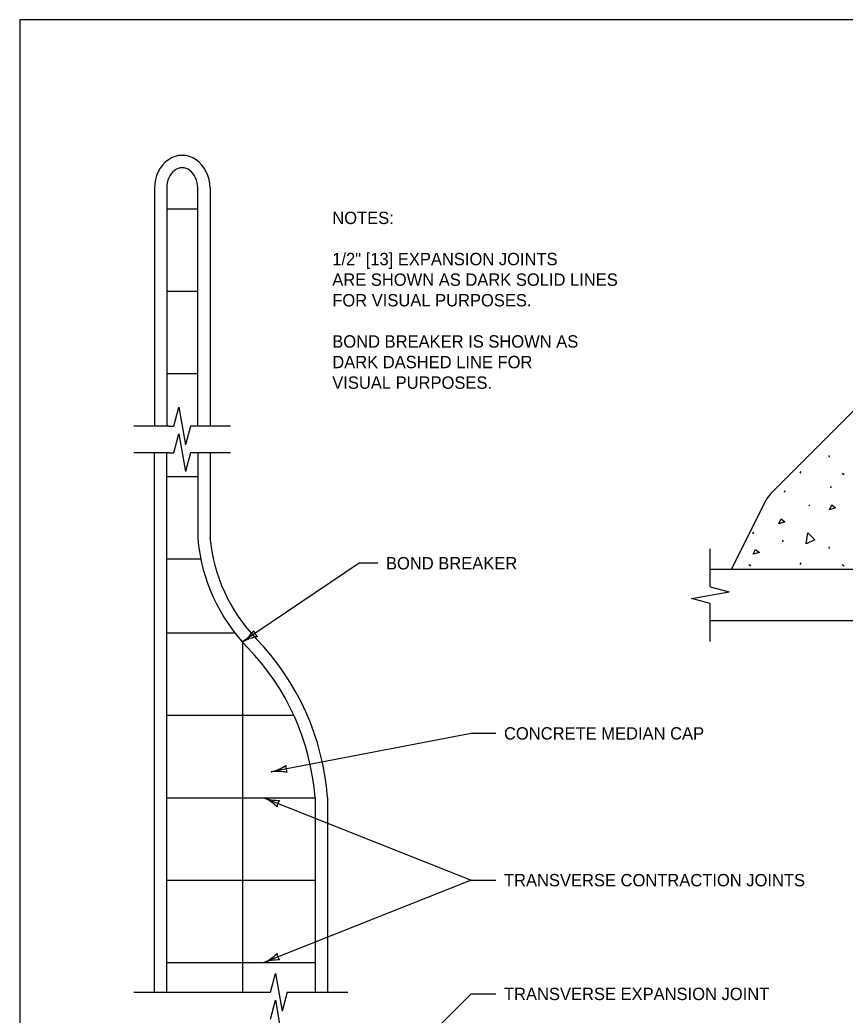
# Model space of a CAD drawing. Extents: x 49991.4 to 50021, y 49987.6 to 50011.4.
# Drawn here: x 50000.336 to 50004.343, y 50006.431 to 50011.263 of the extents above; entities that cross this region are included whole.
import ezdxf

# ---------------------------------------------------------------- set-up
doc = ezdxf.new("R2010")
doc.units = 0
for name, color, linetype in [('Level 1', 7, 'Continuous'), ('Level 2', 7, 'Continuous'), ('Level 3', 7, 'Continuous'), ('Level 6', 7, 'Continuous')]:
    doc.layers.add(name, color=color, linetype=linetype)

msp = doc.modelspace()

# ---------------------------------------------------------------- linework, layer by layer
at = {"layer": 'Level 1'}
for p, q in [((50000.989, 50010.4457), (50000.989, 50009.2907)), ((50001.049, 50010.4457), (50001.049, 50009.2907)), ((50001.199, 50009.2907), (50001.199, 50010.4457)), ((50001.259, 50010.4457), (50001.259, 50009.2907)), ((50001.049, 50010.3457), (50001.199, 50010.3457)), ((50001.049, 50009.9457), (50001.199, 50009.9457)), ((50004.637, 50009.6178), (50003.9828, 50008.9636)), ((50001.049, 50009.5457), (50001.199, 50009.5457)), ((50000.989, 50006.5411), (50000.989, 50009.1609)), ((50001.049, 50006.5411), (50001.049, 50009.1609)), ((50001.199, 50009.1609), (50001.199, 50008.7457)), ((50001.259, 50009.1609), (50001.259, 50008.7457)), ((50004.2649, 50009.1474), (50004.2658, 50009.1389)), ((50001.049, 50009.0462), (50001.199, 50009.0462)), ((50004.1258, 50009.0613), (50004.1296, 50009.0698)), ((50004.3295, 50009.0613), (50004.3333, 50009.0556)), ((50004.3333, 50009.0592), (50004.3371, 50009.0535)), ((50004.2736, 50008.9911), (50004.2774, 50008.9996)), ((50004.0491, 50008.9693), (50004.0529, 50008.9778)), ((50003.958, 50008.9292), (50003.7905, 50008.5943)), ((50004.1675, 50008.9087), (50004.1713, 50008.903)), ((50003.8956, 50008.7675), (50003.8994, 50008.776)), ((50004.0396, 50008.7287), (50004.0434, 50008.7372)), ((50004.2649, 50008.7049), (50004.2658, 50008.6964)), ((50001.049, 50008.6462), (50001.2137, 50008.6462)), ((50003.8757, 50008.6188), (50003.8795, 50008.6131)), ((50003.8795, 50008.6166), (50003.8833, 50008.6109)), ((50004.1258, 50008.6188), (50004.1296, 50008.6273)), ((50004.3295, 50008.6188), (50004.3333, 50008.6131)), ((50004.3333, 50008.6166), (50004.3371, 50008.6109)), ((50003.7906, 50008.5944), (50003.6881, 50008.5944)), ((50005.9155, 50008.5943), (50003.7905, 50008.5943)), ((50006.8155, 50008.3444), (50003.6881, 50008.3444)), ((50001.3799, 50008.2857), (50001.049, 50008.2857)), ((50001.4159, 50008.2423), (50001.4159, 50006.5411)), ((50001.6663, 50007.8857), (50001.049, 50007.8857)), ((50001.049, 50007.4857), (50001.769, 50007.4857)), ((50001.769, 50007.4857), (50001.769, 50006.5411)), ((50001.829, 50007.4878), (50001.829, 50006.5411)), ((50001.049, 50007.0857), (50001.769, 50007.0857)), ((50001.049, 50006.6857), (50001.769, 50006.6857))]:
    msp.add_line(p, q, dxfattribs=at)
msp.add_lwpolyline([(50008.6146, 50011.2628), (50000.3356, 50011.2628), (50000.3356, 50000.0624), (50008.6146, 50000.0624)], close=True, dxfattribs=at)
for points in [[(50004.267, 50008.884), (50004.2784, 50008.9077), (50004.2973, 50008.8935), (50004.267, 50008.884)], [(50004.0209, 50008.8163), (50004.0322, 50008.84), (50004.0512, 50008.8258), (50004.0209, 50008.8163)], [(50004.1549, 50008.7189), (50004.1624, 50008.773), (50004.1963, 50008.738), (50004.1558, 50008.7192)], [(50003.8975, 50008.668), (50003.9089, 50008.6917), (50003.9278, 50008.6775), (50003.8975, 50008.668)]]:
    msp.add_lwpolyline(points, dxfattribs=at)
for centre, radius, start, end in [((50004.0768, 50008.8698), 0.1328, 135, 153.4329), ((50002.0724, 50008.8235), 0.8168, 185.0967, 223.8607), ((50002.0724, 50008.8235), 0.8768, 185.0967, 223.8607), ((50000.6011, 50007.3989), 1.2312, 4.141, 44.2364), ((50000.6011, 50007.3989), 1.1712, 4.2458, 44.2364)]:
    msp.add_arc(centre, radius, start, end, dxfattribs=at)
for major_axis, ratio in [((0, 0.1595), 0.846422), ((0, 0.0995), 0.753807)]:
    msp.add_ellipse((50001.124, 50010.4457), major_axis=major_axis, ratio=ratio, start_param=4.712389, end_param=7.853982, dxfattribs=at)
at = {"layer": 'Level 3'}
for p, q in [((50001.9833, 50008.6255), (50001.4159, 50008.2423)), ((50002.0735, 50008.6255), (50001.9833, 50008.6255)), ((50002.5266, 50007.7984), (50001.556, 50007.6117)), ((50002.6466, 50007.7984), (50002.5266, 50007.7984)), ((50001.52, 50007.4857), (50002.5266, 50007.0857)), ((50002.5266, 50007.0857), (50001.52, 50006.6857)), ((50002.5266, 50007.0857), (50002.6466, 50007.0857)), ((50001.4789, 50005.4857), (50002.5266, 50006.5333)), ((50002.5266, 50006.5333), (50002.6466, 50006.5333))]:
    msp.add_line(p, q, dxfattribs=at)
for centre, radius, start, end in [((50001.2837, 50008.4342), 0.233, 304.565, 323.8148), ((50001.5249, 50008.0486), 0.2223, 99.1937, 119.3772), ((50001.5249, 50008.3098), 0.0548, 193.8765, 229.5988), ((50001.5015, 50007.8382), 0.233, 283.5278, 302.7777), ((50001.682, 50007.6355), 0.0548, 172.8394, 208.5617), ((50001.5882, 50007.3917), 0.2223, 78.1565, 98.3401), ((50001.4294, 50007.2826), 0.2223, 45.756, 65.9395), ((50001.5954, 50007.7061), 0.233, 251.1273, 270.3772), ((50001.6392, 50007.4382), 0.0548, 140.4388, 176.1612), ((50001.4233, 50006.8976), 0.233, 294.5273, 313.7772), ((50001.6392, 50006.7331), 0.0548, 183.8388, 219.5612), ((50001.5937, 50006.4759), 0.2223, 89.156, 109.3395)]:
    msp.add_arc(centre, radius, start, end, dxfattribs=at)
at = {"layer": 'Level 6'}
for p, q in [((50001.0836, 50009.2907), (50001.1078, 50009.3821)), ((50001.1078, 50009.3821), (50001.1402, 50009.1993)), ((50001.0593, 50009.2907), (50000.889, 50009.2907)), ((50001.0593, 50009.2907), (50001.0755, 50009.2907)), ((50001.0755, 50009.2907), (50001.0836, 50009.2907)), ((50001.1646, 50009.2907), (50001.1402, 50009.1993)), ((50001.1727, 50009.2907), (50001.1646, 50009.2907)), ((50001.1889, 50009.2907), (50001.1727, 50009.2907)), ((50001.359, 50009.2907), (50001.1889, 50009.2907)), ((50001.0836, 50009.1609), (50001.1078, 50009.2523)), ((50001.1078, 50009.2523), (50001.1402, 50009.0695)), ((50001.0593, 50009.1609), (50000.889, 50009.1609)), ((50001.0593, 50009.1609), (50001.0755, 50009.1609)), ((50001.0755, 50009.1609), (50001.0836, 50009.1609)), ((50001.1646, 50009.1609), (50001.1402, 50009.0695)), ((50001.1727, 50009.1609), (50001.1646, 50009.1609)), ((50001.1889, 50009.1609), (50001.1727, 50009.1609)), ((50001.359, 50009.1609), (50001.1889, 50009.1609)), ((50003.6881, 50008.5097), (50003.6881, 50008.6944)), ((50003.6881, 50008.5097), (50003.7795, 50008.4853)), ((50003.5967, 50008.4529), (50003.7795, 50008.4853)), ((50003.6881, 50008.4287), (50003.5967, 50008.4529)), ((50003.6881, 50008.2444), (50003.6881, 50008.4287)), ((50001.552, 50006.5411), (50001.5762, 50006.6325)), ((50001.5762, 50006.6325), (50001.6086, 50006.4497)), ((50000.889, 50006.5411), (50001.552, 50006.5411)), ((50001.633, 50006.5411), (50001.6086, 50006.4497)), ((50001.633, 50006.5411), (50001.929, 50006.5411)), ((50001.552, 50006.4113), (50001.5762, 50006.5027)), ((50001.5762, 50006.5027), (50001.6086, 50006.3199))]:
    msp.add_line(p, q, dxfattribs=at)

# ---------------------------------------------------------------- texts
at = {"layer": 'Level 2'}
for s, p in [('NOTES:', (50001.8527, 50010.2716)), ('1/2" [13] EXPANSION JOINTS', (50001.8527, 50010.0716)), ('ARE SHOWN AS DARK SOLID LINES', (50001.8527, 50009.9716)), ('FOR VISUAL PURPOSES.', (50001.8527, 50009.8716)), ('BOND BREAKER IS SHOWN AS', (50001.8527, 50009.6716)), ('DARK DASHED LINE FOR', (50001.8527, 50009.5716)), ('VISUAL PURPOSES.', (50001.8527, 50009.4716)), ('BOND BREAKER', (50002.1135, 50008.5946)), ('CONCRETE MEDIAN CAP', (50002.6866, 50007.7684)), ('TRANSVERSE CONTRACTION JOINTS', (50002.6866, 50007.0557)), ('TRANSVERSE EXPANSION JOINT', (50002.6866, 50006.5034))]:
    msp.add_text(s, height=0.06, dxfattribs=at).set_placement(p)

doc.saveas('drawing.dxf')
